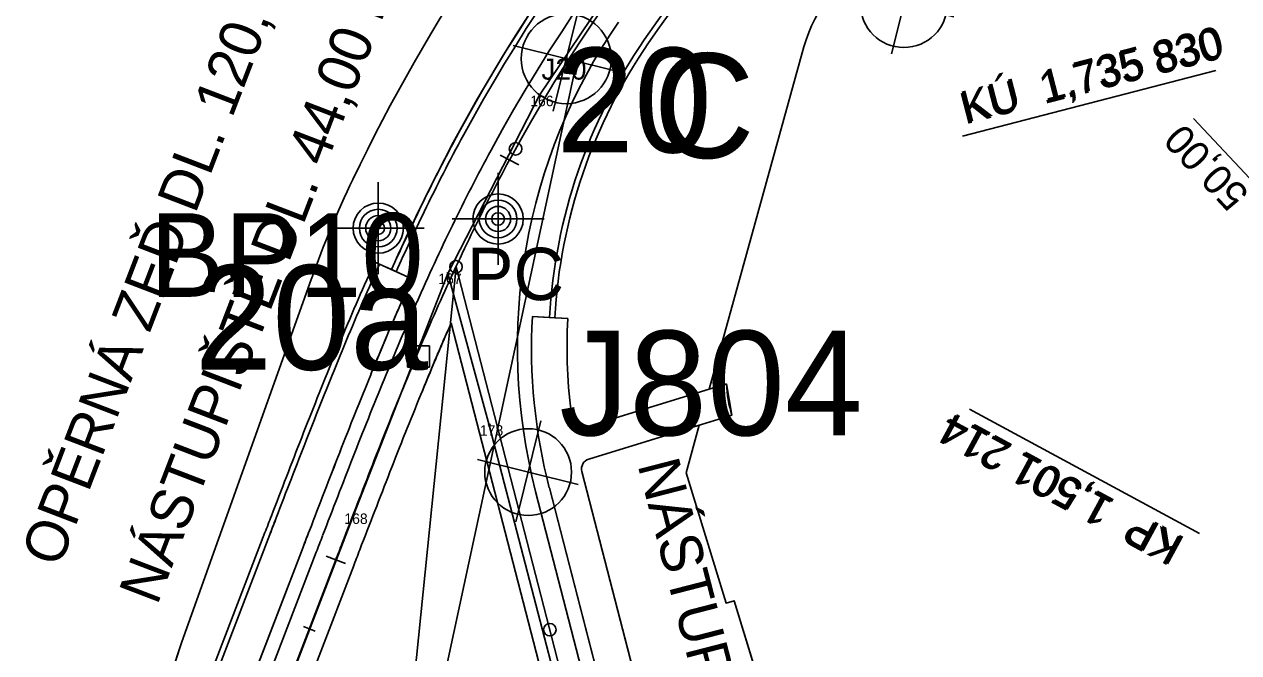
# Model space of a CAD drawing. Extents: x -606444 to -604546, y -1158114 to -1156869.
# Drawn here: x -606212 to -606096, y -1157434 to -1157373.9 of the extents above; entities that cross this region are included whole.
import ezdxf

# ---------------------------------------------------------------- set-up
doc = ezdxf.new("R2010")
doc.units = 0
for name, color, linetype in [('0_sondy', 7, 'Continuous'), ('ARCHIVNÍ SONDY', 7, 'Continuous'), ('B_CHOD', 7, 'Continuous'), ('B_TRAM', 7, 'Continuous'), ('B_ZELEN', 7, 'Continuous'), ('geofyzikální profily_předběžný GTP', 7, 'Continuous'), ('GF řezy', 7, 'Continuous'), ('jádrové vrty_předběžný GTP', 7, 'Continuous'), ('korozní průzkum', 7, 'Continuous'), ('netisk2', 7, 'Continuous'), ('NS_VB', 7, 'Continuous'), ('NS_VB_OBJ', 7, 'Continuous'), ('NS_VB_POP', 7, 'Continuous'), ('OSA', 7, 'Continuous'), ('OSAPOP', 7, 'Continuous'), ('podélný profil trasou tramvaje', 7, 'Continuous'), ('Sondy 2', 7, 'Continuous'), ('sondy předběžného průzkumu', 7, 'Continuous'), ('sondy současného průzkumu', 7, 'Continuous')]:
    doc.layers.add(name, color=color, linetype=linetype)

# ---------------------------------------------------------------- blocks, each defined once
blk = doc.blocks.new('709')
for p, q in [((0, 2.2), (0, -2.2)), ((-2.2, 0), (2.2, 0))]:
    blk.add_line(p, q)
for radius in [1.2, 0.9, 0.6, 0.3]:
    blk.add_circle((0, 0), radius)
blk = doc.blocks.new('IG vrt podr')
at = {"layer": 'sondy současného průzkumu'}
for p, q in [((0.412, 1.649), (-0.418, -1.672)), ((-1.698, 0.422), (1.644, -0.408))]:
    blk.add_line(p, q, dxfattribs=at)
blk.add_circle((-0.002, 0.001), 1.434, dxfattribs=at)
blk = doc.blocks.new('IG vrt archivní')
at = {"layer": 'sondy předběžného průzkumu'}
for p, q in [((0.406, 1.636), (-0.393, -1.584)), ((1.589, -0.397), (-1.612, 0.402))]:
    blk.add_line(p, q, dxfattribs=at)
blk.add_circle((0.001, 0.002), 1.382, dxfattribs=at)

msp = doc.modelspace()

# ---------------------------------------------------------------- linework, layer by layer
for p, q in [((-606160.25, -1157377.21), (-606160.35, -1157377.11)), ((-606160.25, -1157377.21), (-606160.35, -1157377.31)), ((-606160.25, -1157377.21), (-606160.15, -1157377.11)), ((-606160.25, -1157377.21), (-606160.15, -1157377.31)), ((-606162.75, -1157380.75), (-606162.85, -1157380.65)), ((-606162.75, -1157380.75), (-606162.85, -1157380.85)), ((-606162.75, -1157380.75), (-606162.65, -1157380.65)), ((-606162.75, -1157380.75), (-606162.65, -1157380.85)), ((-606171.56, -1157397.75), (-606171.66, -1157397.65)), ((-606171.56, -1157397.75), (-606171.66, -1157397.85)), ((-606171.56, -1157397.75), (-606171.46, -1157397.65)), ((-606171.56, -1157397.75), (-606171.46, -1157397.85)), ((-606167.61, -1157412.25), (-606167.71, -1157412.15)), ((-606167.61, -1157412.25), (-606167.71, -1157412.35)), ((-606167.61, -1157412.25), (-606167.51, -1157412.15)), ((-606167.61, -1157412.25), (-606167.51, -1157412.35)), ((-606180.53, -1157420.69), (-606180.63, -1157420.59)), ((-606180.53, -1157420.69), (-606180.63, -1157420.79)), ((-606180.53, -1157420.69), (-606180.43, -1157420.59)), ((-606180.53, -1157420.69), (-606180.43, -1157420.79))]:
    msp.add_line(p, q)
at = {"layer": 'B_CHOD'}
for p, q in [((-606178.86, -1157398.55), (-606178.1, -1157396.86)), ((-606178.1, -1157396.86), (-606175, -1157398.25)), ((-606175, -1157398.25), (-606175.76, -1157399.95)), ((-606163.5, -1157401.86), (-606160.1, -1157402.05)), ((-606158.43, -1157412.45), (-606144.94, -1157408.31)), ((-606144.94, -1157408.31), (-606144.44, -1157411.29)), ((-606144.44, -1157411.29), (-606158.09, -1157415.49)), ((-606158.76, -1157416.69), (-606146.42, -1157464.5)), ((-606153.21, -1157451.81), (-606161.87, -1157418.25)), ((-606203.37, -1157461.27), (-606188.58, -1157422.7)), ((-606185.41, -1157423.91), (-606193.75, -1157445.68))]:
    msp.add_line(p, q, dxfattribs=at)
for centre, radius, start, end in [((-605891.31, -1157525.22), 314.22, 156.2259, 157.7167), ((-605891.31, -1157525.22), 310.82, 156.2307, 157.7167), ((-606109.93, -1157404.83), 53.65, 176.8274, 194.4799), ((-606109.93, -1157404.83), 50.25, 176.8274, 187.7775), ((-605725.17, -1157593.3), 493.76, 157.7167, 158.6579), ((-605725.17, -1157593.3), 490.36, 157.7167, 158.6589), ((-606158.72, -1157411.5), 1, 187.7775, 287.079), ((-605088.53, -1157842.06), 1177.27, 158.65787, 159.04934), ((-605088.53, -1157842.06), 1173.87, 158.65829, 159.0494), ((-606157.8, -1157416.44), 1, 107.079, 194.4799), ((-598853.59, -1160235.67), 7855.89, 159.005753, 159.018142), ((-598853.42, -1160235.74), 7852.67, 159.005744, 159.018143)]:
    msp.add_arc(centre, radius, start, end, dxfattribs=at)
at = {"layer": 'B_TRAM'}
for points in [[(-606175, -1157398.25), (-606176.96, -1157397.37)], [(-606161.35, -1157401.98), (-606163.5, -1157401.86)], [(-606161.87, -1157418.25), (-606154.46, -1157446.96), (-606159.44, -1157448.25), (-606171.26, -1157402.51)], [(-606180.6, -1157425.76), (-606187.15, -1157442.85), (-606191.96, -1157441.01), (-606185.41, -1157423.91)]]:
    msp.add_lwpolyline(points, dxfattribs=at)
for centre, radius, start, end in [((-606024.98, -1157463.17), 165.56, 102.3924, 154.3928), ((-606025, -1157463.12), 154.5, 102.3876, 145.5388), ((-606109.93, -1157404.83), 51.5, 145.5388, 176.8274), ((-605967.1, -1157491.84), 230.15, 154.1855, 155.7657), ((-605967.1, -1157491.84), 228, 155.7657, 156.2259), ((-605891.31, -1157525.22), 310.82, 156.2259, 157.7167), ((-606109.93, -1157404.83), 53.65, 176.8274, 194.4799), ((-605891.31, -1157525.22), 305.67, 156.3302, 157.7167), ((-605725.17, -1157593.3), 490.36, 157.7167, 158.6579), ((-605725.17, -1157593.3), 485.21, 157.7167, 158.6579), ((-605088.53, -1157842.06), 1173.87, 158.65787, 159.0494), ((-605088.53, -1157842.06), 1168.72, 158.65787, 159.0495), ((-598853.41, -1160235.74), 7852.68, 159.005744, 159.018143), ((-598853.34, -1160235.77), 7847.6, 159.00573, 159.018144)]:
    msp.add_arc(centre, radius, start, end, dxfattribs=at)
at = {"layer": 'B_ZELEN'}
for points in [[(-606137.55, -1157376.08), (-606146.6, -1157408.82), (-606158.43, -1157412.45)], [(-606176.96, -1157397.37), (-606178.1, -1157396.86)], [(-606180.37, -1157505.2), (-606204.91, -1157486.44), (-606209.23, -1157480.22), (-606209.99, -1157477.97), (-606210.51, -1157475.22), (-606210.8, -1157473.01), (-606210.84, -1157470.86), (-606208.44, -1157462.93), (-606205.75, -1157457.23), (-606201.9, -1157447.85), (-606197.03, -1157433.07), (-606184.6, -1157398.24)], [(-606159.44, -1157448.25), (-606171.26, -1157402.51)], [(-606160.1, -1157402.05), (-606161.35, -1157401.98)], [(-606158.09, -1157415.49), (-606147.55, -1157412.25), (-606148.81, -1157416.81), (-606144.99, -1157429.26), (-606144.22, -1157429.03), (-606127.99, -1157481.87), (-606118.09, -1157478.83), (-606117.15, -1157481.89), (-606120.01, -1157483.46)], [(-606146.42, -1157464.5), (-606158.76, -1157416.69)], [(-606188.58, -1157422.7), (-606203.37, -1157461.27)], [(-606180.6, -1157425.76), (-606187.15, -1157442.85), (-606174.61, -1157447.67)]]:
    msp.add_lwpolyline(points, dxfattribs=at)
for centre, radius, start, end in [((-606025, -1157463.12), 165.5, 102.3874, 151.5505), ((-606025, -1157463.12), 154.5, 102.3875, 145.5388), ((-606025, -1157463.12), 172.5, 121.038, 154.4605), ((-606124.1, -1157379.8), 13.95, 117.5817, 164.5679), ((-606109.93, -1157404.83), 51.5, 145.5388, 176.8274), ((-606015.39, -1157468.33), 176.44, 151.5505, 154.2299), ((-606090.42, -1157431.86), 100, 154.4605, 160.358), ((-605954.69, -1157497.63), 243.83, 154.2299, 155.7214), ((-605967.1, -1157491.84), 231.4, 155.7657, 156.2259), ((-605891.31, -1157525.22), 314.22, 156.2259, 157.7167), ((-605891.31, -1157525.22), 305.67, 156.3302, 156.572), ((-606109.93, -1157404.83), 50.25, 176.8274, 187.7775), ((-605891.31, -1157525.22), 305.67, 156.572, 157.7167), ((-605725.17, -1157593.3), 493.76, 157.7167, 158.6579), ((-605725.17, -1157593.3), 485.21, 157.7167, 158.6578), ((-606158.72, -1157411.5), 1, 187.7775, 287.079), ((-605088.53, -1157842.06), 1177.27, 158.65787, 159.04934), ((-606157.8, -1157416.44), 1, 107.079, 194.4799), ((-605088.53, -1157842.06), 1168.72, 158.65786, 159.0495), ((-607403.32, -1156955.78), 1301.39, 338.97455, 339.04934), ((-598853.34, -1160235.77), 7847.6, 159.00573, 159.018144)]:
    msp.add_arc(centre, radius, start, end, dxfattribs=at)
at = {"layer": 'geofyzikální profily_předběžný GTP'}
msp.add_line((-606159.26, -1157377.45), (-606182.42, -1157485.12), dxfattribs=at)
at = {"layer": 'GF řezy'}
msp.add_line((-606170.79, -1157397.11), (-606179.86, -1157486.65), dxfattribs=at)
at = {"layer": 'korozní průzkum'}
msp.add_lwpolyline([(-606175.42, -1157404.67), (-606173.34, -1157404.67), (-606173.34, -1157406.7), (-606175.42, -1157406.7)], close=True, dxfattribs=at)
at = {"layer": 'netisk2'}
msp.add_line((-606160.25, -1157377.21), (-606160.06, -1157377.33), dxfattribs=at)
at = {"layer": 'NS_VB'}
for p, q in [((-606137.55, -1157376.08), (-606146.6, -1157408.82)), ((-606175, -1157398.25), (-606178.1, -1157396.86)), ((-606184.6, -1157398.24), (-606197.03, -1157433.07)), ((-606163.5, -1157401.86), (-606160.1, -1157402.05)), ((-606144.94, -1157408.31), (-606158.43, -1157412.45)), ((-606144.44, -1157411.29), (-606158.09, -1157415.49)), ((-606147.55, -1157412.25), (-606148.81, -1157416.81)), ((-606146.42, -1157464.5), (-606158.76, -1157416.69)), ((-606148.81, -1157416.81), (-606144.99, -1157429.26)), ((-606153.21, -1157451.81), (-606161.87, -1157418.25)), ((-606188.58, -1157422.7), (-606203.37, -1157461.27)), ((-606185.41, -1157423.91), (-606193.75, -1157445.68)), ((-606144.99, -1157429.26), (-606144.22, -1157429.03)), ((-606144.22, -1157429.03), (-606127.99, -1157481.87)), ((-606197.03, -1157433.07), (-606201.9, -1157447.85))]:
    msp.add_line(p, q, dxfattribs=at)
for points in [[(-606159.44, -1157448.25), (-606171.26, -1157402.51)], [(-606180.6, -1157425.76), (-606187.15, -1157442.85)]]:
    msp.add_lwpolyline(points, dxfattribs=at)
for centre, radius, start, end in [((-606025, -1157463.12), 165.5, 102.3874, 151.5505), ((-606025, -1157463.12), 154.5, 102.3875, 145.5388), ((-606025, -1157463.12), 172.5, 121.038, 154.4605), ((-606124.1, -1157379.8), 13.95, 117.5817, 164.5679), ((-606109.93, -1157404.83), 51.5, 145.5388, 176.8274), ((-606010.01, -1157471.08), 182.48, 151.5948, 154.1855), ((-606090.42, -1157431.86), 100, 154.4605, 160.358), ((-605967.1, -1157491.84), 230.15, 154.1855, 155.7657), ((-605967.1, -1157491.84), 231.4, 155.7657, 156.2259), ((-605967.1, -1157491.84), 228, 155.7657, 156.2259), ((-605891.31, -1157525.22), 314.22, 156.2259, 157.7167), ((-605891.31, -1157525.22), 310.82, 156.2259, 157.7167), ((-606109.93, -1157404.83), 53.65, 176.8274, 194.4799), ((-605891.31, -1157525.22), 305.67, 156.3302, 157.7167), ((-606109.93, -1157404.83), 50.25, 176.8274, 187.7775), ((-605725.17, -1157593.3), 493.76, 157.7167, 158.6579), ((-605725.17, -1157593.3), 490.36, 157.7167, 158.6579), ((-606131.81, -1157407.65), 13.15, 182.89, 196.1058), ((-605725.17, -1157593.3), 485.21, 157.7167, 158.6579), ((-606158.72, -1157411.5), 1, 187.7775, 287.079), ((-605088.53, -1157842.06), 1177.27, 158.65787, 159.04934), ((-605088.53, -1157842.06), 1173.87, 158.65787, 159.0494), ((-606157.8, -1157416.44), 1, 107.079, 194.4799), ((-605088.53, -1157842.06), 1168.72, 158.65787, 159.0495), ((-598853.33, -1160235.77), 7856.16, 159.005753, 159.018143), ((-598853.33, -1160235.77), 7852.76, 159.005744, 159.018143), ((-598853.34, -1160235.77), 7847.6, 159.00573, 159.018144)]:
    msp.add_arc(centre, radius, start, end, dxfattribs=at)
at = {"layer": 'NS_VB_OBJ'}
for points in [[(-606176.51, -1157397.57), (-606178.56, -1157396.65)], [(-606189.05, -1157422.52), (-606203.84, -1157461.09)]]:
    msp.add_lwpolyline(points, dxfattribs=at)
for centre, radius, start, end in [((-606025, -1157463.12), 165, 108.142, 151.5504), ((-606025, -1157463.12), 155, 108.142, 145.5388), ((-606109.93, -1157404.83), 52, 145.5388, 176.8274), ((-606010.01, -1157471.08), 181.98, 151.5949, 154.1855), ((-605967.1, -1157491.84), 229.65, 154.1855, 155.7657), ((-605967.1, -1157491.84), 231.9, 155.7657, 156.2259), ((-605891.31, -1157525.22), 314.72, 156.2259, 157.7167), ((-605725.17, -1157593.3), 494.26, 157.7167, 158.6579), ((-605088.53, -1157842.06), 1177.77, 158.65787, 159.04933), ((-598853.33, -1160235.77), 7856.66, 159.005755, 159.018143)]:
    msp.add_arc(centre, radius, start, end, dxfattribs=at)
at = {"layer": 'OSA'}
for p, q in [((-606153.5, -1157464.08), (-606170.79, -1157397.11)), ((-606182.28, -1157425.11), (-606196.29, -1157461.65))]:
    msp.add_line(p, q, dxfattribs=at)
for points in [[(-606151.02, -1157465.69), (-606163.18, -1157418.59)], [(-606184.14, -1157424.4), (-606198.94, -1157462.97)]]:
    msp.add_lwpolyline(points, dxfattribs=at)
for centre, radius, start, end in [((-606025, -1157463.12), 162, 102.3874, 151.55), ((-606025, -1157463.12), 160, 102.3874, 151.5497), ((-606109.93, -1157404.83), 55, 145.5388, 194.4799), ((-606010.01, -1157471.08), 178.98, 151.5953, 154.1855), ((-606010.01, -1157471.08), 176.98, 151.5955, 154.1855), ((-605967.1, -1157491.84), 226.65, 154.1855, 156.2259), ((-605967.1, -1157491.84), 224.65, 154.1855, 156.2259), ((-605891.31, -1157525.22), 309.47, 156.2259, 157.7167), ((-605891.31, -1157525.22), 307.47, 156.2259, 157.7167), ((-605725.17, -1157593.3), 489.01, 157.7167, 158.6579), ((-605725.17, -1157593.3), 487.01, 157.7167, 158.6579), ((-605088.53, -1157842.06), 1172.52, 158.65787, 159.04943), ((-605088.53, -1157842.06), 1170.52, 158.65787, 159.04947), ((-598853.34, -1160235.77), 7851.4, 159.00574, 159.018143), ((-598853.33, -1160235.77), 7849.41, 159.005735, 159.018144)]:
    msp.add_arc(centre, radius, start, end, dxfattribs=at)
at = {"layer": 'OSAPOP'}
for p, q in [((-606093.47, -1157390.23), (-606100.32, -1157382.94)), ((-606164.8, -1157387.37), (-606166.56, -1157386.42)), ((-606099.74, -1157422.62), (-606121.72, -1157410.71)), ((-606181.34, -1157425.47), (-606183.21, -1157424.76)), ((-606184.25, -1157431.94), (-606185.37, -1157431.51))]:
    msp.add_line(p, q, dxfattribs=at)
msp.add_lwpolyline([(-606122.38, -1157384.6), (-606098.18, -1157378.35)], dxfattribs=at)
for centre in [(-606165.1, -1157385.83), (-606170.79, -1157397.11), (-606161.83, -1157431.8)]:
    msp.add_circle(centre, 0.6, dxfattribs=at)
at = {"layer": 'podélný profil trasou tramvaje'}
for points in [[(-605949.82, -1157295.6), (-605999.99, -1157299.9), (-606029.31, -1157302.59), (-606037.05, -1157303.31), (-606055.2, -1157306.01), (-606073.75, -1157309.95), (-606079.24, -1157312.23), (-606082.05, -1157313.33), (-606094.93, -1157318.61), (-606110.15, -1157327.53), (-606116.44, -1157331.17), (-606138.24, -1157349.34), (-606153.99, -1157367.55), (-606162.8, -1157380.7), (-606171.56, -1157397.75), (-606180.53, -1157420.69), (-606192.65, -1157452.3), (-606195.21, -1157458.76), (-606195.21, -1157458.76), (-606195.33, -1157460.2), (-606196.07, -1157462.31), (-606197.75, -1157467.6), (-606193.13, -1157485.08)], [(-606155.06, -1157460.99), (-606161.14, -1157437.22), (-606167.61, -1157412.25), (-606171.56, -1157397.75)]]:
    msp.add_lwpolyline(points, dxfattribs=at)

# ---------------------------------------------------------------- block references
at = {"layer": '0_sondy', "xscale": 2, "yscale": 2}
msp.add_blockref('709', (-606166.77, -1157392.53), dxfattribs=at)
at = {"layer": 'ARCHIVNÍ SONDY', "xscale": 3, "yscale": 3}
for p in [(-606128, -1157372), (-606163.9, -1157416.74)]:
    msp.add_blockref('IG vrt archivní', p, dxfattribs=at)
at = {"layer": 'jádrové vrty_předběžný GTP', "xscale": 3, "yscale": 3}
msp.add_blockref('IG vrt podr', (-606160.25, -1157377.21), dxfattribs=at)
at = {"layer": 'Sondy 2', "xscale": 2, "yscale": 2}
msp.add_blockref('709', (-606178.22, -1157393.41), dxfattribs=at)

# ---------------------------------------------------------------- texts
for s, height, p in [('J20', 2, (-606162.63, -1157379.21)), ('166', 1, (-606163.7, -1157381.75)), ('167', 1, (-606172.49, -1157398.75)), ('178', 1, (-606168.51, -1157413.25)), ('168', 1, (-606181.46, -1157421.69))]:
    msp.add_text(s, height=height).set_placement(p)
at = {"layer": '0_sondy'}
msp.add_text('20', height=10, dxfattribs=at).set_placement((-606161.21, -1157386.17))
at = {"layer": 'ARCHIVNÍ SONDY'}
msp.add_text('J804', height=10, dxfattribs=at).set_placement((-606160.93, -1157413.22))
at = {"layer": 'geofyzikální profily_předběžný GTP'}
msp.add_text('C', height=10, dxfattribs=at).set_placement((-606151.92, -1157386.7))
at = {"layer": 'GF řezy'}
msp.add_text('PC', height=5, dxfattribs=at).set_placement((-606169.76, -1157400.29))
at = {"layer": 'korozní průzkum'}
msp.add_text('BP10', height=8, dxfattribs=at).set_placement((-606200.05, -1157399.98))
at = {"layer": 'NS_VB_POP'}
for s, rotation, p in [('OPĚRNÁ ZEĎ DL. 120,00 m', 69.0161, (-606208.69, -1157425.98)), ('NÁSTUPIŠTĚ DL. 44,00 m', 69.0161, (-606199.35, -1157429.56)), ('NÁSTUPIŠTĚ DL. 44,00 m', 284.4799, (-606153.46, -1157416.02))]:
    msp.add_text(s, height=4, rotation=rotation, dxfattribs=at).set_placement(p)
at = {"layer": 'OSAPOP'}
for s, height, rotation, p in [('KÚ  1,735 830', 3, 14.4799, (-606122.15, -1157383.51)), ('KÚ  1,735 830', 3, 14.4799, (-606122.04, -1157383.33)), ('50,00', 2.8, 133.2101, (-606094.89, -1157390.08)), ('KP  1,501 214', 3, 151.5497, (-606101.21, -1157423.13)), ('KP  1,501 214', 3, 151.5497, (-606101.01, -1157423.07))]:
    msp.add_text(s, height=height, rotation=rotation, dxfattribs=at).set_placement(p)
at = {"layer": 'Sondy 2'}
msp.add_text('20a', height=10, dxfattribs=at).set_placement((-606195.78, -1157406.95))

doc.saveas('drawing.dxf')
